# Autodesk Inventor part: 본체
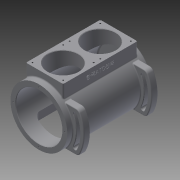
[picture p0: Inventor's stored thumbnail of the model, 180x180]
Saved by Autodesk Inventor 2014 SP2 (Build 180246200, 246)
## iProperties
Created: 2016-11
Part Number: 본체
Material: 알루미늄 6061
Document SubType Name: Modeling
Designer: mduedu
Density: 2.71 g/cm^3
Appearance: 기본값
Author: mduedu
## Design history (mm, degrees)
sketch "스케치1"
  geometry: C1 r 65 at (0, 0); 1 further point
  constraints: 1 centre point, 1 coincident
  dimensions: "d119" = 130 diameter of C1
extrude "돌출1" new body sketch "스케치1" distance "d3" = 98; taper "d4" = 0 deg; dims "d132" = 97, "d133" = 0
feature "쉘1" dims "d120" = 12, "d134" = 8
node "작업 평면2"
sketch "스케치13"
  geometry: L1 (42.5, 85)-(-42.5, 85); L2 (-42.5, 85)-(-42.5, -85); L3 (-42.5, -85)-(42.5, -85); L4 (42.5, -85)-(42.5, 85); 2 further points
  constraints: 8 end point, 2 parallel, 1 horizontal, 1 midpoint, 1 perpendicular, 1 vertical alignment
  dimensions: "d122" = 170 distance of L1.end L2.end; "d124" = 85 distance of L2.end L3.end; "d125" = 85 distance from line of point (0, 0) L1 (= 0.5 x d122)
extrude "돌출11" join sketch "스케치13" stored distance "d126" = 10; taper "d127" = 0 deg
sketch "스케치14"
  geometry: L1 (65, 97)-(-65, 97) reference; C1 r 35 at (0, 42.5); 1 further point
  constraints: 1 centre point, 1 vertical alignment
  dimensions: "d128" = 70 diameter of C1; "d129" = 54.5 distance from line of C1.centre L1
extrude "돌출12" cut sketch "스케치14" stored distance "d130" = 10; taper "d131" = 0 deg
sketch "스케치15"
  geometry: C1 r 53 at (0, 0) reference; 1 further point
extrude "돌출13" cut sketch "스케치15" stored distance "d135" = 10; taper "d136" = 0 deg
chamfer "모따기1" distance "d54" = 1; stored, may be unused: second distance "d55" = 2, angle "d56" = 45 deg
sketch "스케치8"
  geometry: C1 r 23 at (0, 0); C2 r 65 at (0, 0) reference; 1 further point
  constraints: 1 centre point, 1 concentric
  dimensions: "d57" = 46 diameter of C1
extrude "돌출8" join sketch "스케치8" distance "d58" = 14; taper "d59" = 0 deg
hole "구멍3" diameter "d62" = 24; stored, may be unused: countersink angle "d66" = 90 deg, drill point angle "d68" = 0 deg; dims "d63" = 6, "d64" = 28, "d65" = 8, "d67" = 14, "d169" = 10, "d170" = 10
fillet "모깎기11" dims "d69" = 3
fillet "모깎기12" dims "d70" = 3
fillet "모깎기13" dims "d71" = 0.3
chamfer "모따기2" distance "d72" = 1; stored, may be unused: second distance "d73" = 2, angle "d74" = 45 deg
node "작업 평면3"
sketch "스케치16"
  geometry: L1 (-42.5, -80)-(47.5, -80); L2 (-42.5, -80)-(21.14, -16.36); L3 (-42.5, -80)-(21.14, -143.64); L4 (3.462, -34.038)-(34.879, -34.038); L5 (3.462, -125.962)-(34.879, -125.962); A1 r 65 centre (-42.5, -80) between (3.462, -34.038) and (3.462, -125.962) reference; A2 r 90 centre (-42.5, -80) between (34.879, -125.962) and (34.879, -34.038); A3 r 90 centre (-42.5, -80) between (34.879, -34.038) and (34.879, -125.962); A4 r 65 centre (-42.5, -80) between (3.462, -125.962) and (3.462, -34.038); 1 further point
  constraints: 11 point on circle, 10 end point, 3 centre point, 2 parallel, 2 point on line, 1 coincident, 1 horizontal
  dimensions: "d140" = 45 deg angle of L3 L1; "d141" = 45 deg angle of L2 L1; "d142" = 25 radial gap between concentric circles of A1 A2
extrude "돌출14" join sketch "스케치16" distance "d143" = 15; taper "d144" = 0 deg
sketch "스케치17"
  geometry: L1 (-42.5, -80)-(34.414, -80); L2 (-42.5, -80)-(27.208, -47.495); L3 (-42.5, -80)-(27.208, -112.505); L4 (34.879, -34.038)-(3.462, -34.038) reference; L5 (3.462, -125.962)-(34.879, -125.962) reference; A1 r 65 centre (-42.5, -80) between (3.462, -34.038) and (3.462, -125.962) reference; A2 r 76.914 centre (-42.5, -80) between (19.17, -125.962) and (19.17, -34.038); A3 r 4 centre (27.208, -47.495) between (23.582, -49.185) and (30.833, -45.804); A4 r 4 centre (27.208, -112.505) between (30.833, -114.196) and (23.582, -110.815); A5 r 80.914 centre (-42.5, -80) between (30.833, -114.196) and (30.833, -45.804); A6 r 72.914 centre (-42.5, -80) between (23.582, -110.815) and (23.582, -49.185); 1 further point
  constraints: 13 point on circle, 6 end point, 5 centre point, 5 coincident, 3 midpoint, 2 point on line, 1 equal radius, 1 horizontal
  dimensions: "d145" = 25 deg angle of L1 L3; "d146" = 25 deg angle of L2 L1; "d147" = 8 diameter of A3
extrude "돌출15" cut sketch "스케치17" stored distance "d150" = 15; taper "d151" = 0 deg
fillet "모깎기17" dims "d152" = 10
fillet "모깎기18" dims "d153" = 2
fillet "모깎기19" dims "d154" = 2
chamfer "모따기4" distance "d155" = 1; stored, may be unused: second distance "d156" = 2, angle "d157" = 45 deg
fillet "모깎기20" dims "d159" = 3
fillet "모깎기21" dims "d160" = 3
fillet "모깎기22" dims "d161" = 3
node "작업 평면4"
sketch "스케치18"
  geometry: L1 (-42.5, 65)-(42.5, 65); L2 (42.5, 65)-(42.5, -65); L3 (42.5, -65)-(-42.5, -65); L4 (-42.5, -65)-(-42.5, 65); 2 further points
  constraints: 8 end point, 2 parallel, 1 horizontal, 1 midpoint, 1 perpendicular, 1 vertical alignment
  dimensions: "d162" = 130 distance of L1.end L2.end; "d164" = 85 distance of L2.end L3.end; "d165" = 65 distance from line of point (0, 0) L1 (= 0.5 x d162)
extrude "돌출16" cut sketch "스케치18" stored distance "d166" = 15; taper "d167" = 0 deg
fillet "모깎기23" dims "d168" = 10
fillet "모깎기24" dims "d173" = 3
sketch "스케치19"
  geometry: 4 further points
  constraints: 4 other
hole "구멍6" sketch "스케치19" at (0, -59), (59, 0), (-59, 0), (0, 59) diameter "d174" = 3.242; stored, may be unused: countersink angle "d178" = 90 deg, drill point angle "d180" = 120 deg; dims "d175" = 7, "d176" = 4, "d177" = 2, "d179" = 9
sketch "스케치20"
  geometry: L1 (35, -77.5)-(-35, -77.5); L2 (-35, -77.5)-(-35, -7.5); L3 (-35, -7.5)-(35, -7.5); L4 (35, -7.5)-(35, -77.5); L5 (35, -77.5)-(-35, -7.5); L6 (-35, -77.5)-(35, -7.5); C1 r 36 at (0, -42.5) reference; 5 further points
  constraints: 12 end point, 4 coincident, 2 midpoint, 2 parallel, 1 horizontal, 1 perpendicular
  dimensions: "d181" = 70 distance of L2.end L3.end; "d182" = 70 distance of L1.end L2.end
hole "구멍7" sketch "스케치20" at (-35, -77.5), (-35, -7.5), (35, -7.5), (35, -77.5) diameter "d183" = 3.242; stored, may be unused: countersink angle "d187" = 90 deg, drill point angle "d189" = 118 deg; dims "d184" = 7, "d185" = 4, "d186" = 2, "d188" = 9
sketch "스케치21"
  geometry: L1 (164, 0)-(0, 0) reference; L2 (-3, 0)-(-3, -24.649) reference; 3 further points
  constraints: 1 midpoint, 1 vertical alignment, 1 other
  dimensions: "d190" = 15 distance from line of point (82, -15) L1; "d191" = 85 distance from line of point (82, 0) L2 (derived)
feature "엠보싱2" sketch "스케치21" dims "d3" = 98, "d4" = 0, "d119" = 130, "d132" = 97, "d133" = 0, "d192" = 0.5, "d193" = 0
node "솔리드1"
mirror "대칭5"
mirror "대칭6"
mirror "대칭7"
